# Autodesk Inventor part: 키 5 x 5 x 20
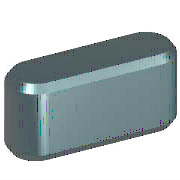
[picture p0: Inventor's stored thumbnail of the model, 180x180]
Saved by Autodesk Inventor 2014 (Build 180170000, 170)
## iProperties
IsCustomPart: 1
Created: 2012-02
Part Number: 키 5 x 5 x 20
Material: 강철, 연강
Description: 키 및 해당 키홈
Document SubType Name: Modeling
Standard: KS B 1311
Designer: mduedu
Standards Organization: KS
Language: ko-KR
Size Designation: 5 x 5 x 20
Categories: <MemberInstance><Categories><Category DisplayName="샤프트 부품" InternalName="7f7aeb1f-a693-4053-b835-cee3144e0d98" Mnemonic="SHFT"><Category DisplayName="키" Interna
Density: 1 g/cm^3
Appearance: 노란색
Author: mduedu
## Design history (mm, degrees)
workplane "Work Plane1"
workplane "Work Plane2"
sketch "스케치1"
  geometry: L1 (2.5, 2.5)-(17.5, 2.5); L2 (17.5, -2.5)-(2.5, -2.5); L3 (0, 9.4)-(0, -7.4) reference; L4 (-5, 0)-(30, 0) reference; L5 (20, 0)-(20, 7); A1 r 2.5 centre (2.5, 0) between (2.5, 2.5) and (2.5, -2.5); A2 r 2.5 centre (17.5, 0) between (17.5, -2.5) and (17.5, 2.5)
  constraints: 6 end point, 5 point on circle, 4 tangent, 3 point on line, 2 centre point, 1 horizontal, 1 parallel, 1 perpendicular
  dimensions: "d0" = 2.5 radius of A1 (= 0.5 x PB); "d13" = 2.5 radius of A2 (= 0.5 x PB); "d14" = 20 distance between parallel lines of L5 L3 (= NLG)
extrude "본체1" new body sketch "스케치1" taper "d3" = 0 deg; stored distance "d4" = 10
workplane "Work Plane3"
body "Solid1"
chamfer "모따기1" distance "d8" = 0.4 (= PHH); stored, may be unused: second distance "d9" = 0.4 (= PHH), angle "d15" = 45 deg
other parameters: "d1" = -3 (= -PNT), "d2" = 2 (= PH - PNT), "NLG" = 20 [user parameter; used in 3 equation terms], "PB" = 5 [user parameter; used in 2 equation terms], "PNT" = 3 [user parameter; used in 2 equation terms], "PH" = 5 [user parameter; used in 1 equation term], "PHH" = 0.4 [user parameter; used in 2 equation terms], "d10" = 0, "d16" = 0, "d17" = 0, "d18" = 0, "WDMIN" = 12 [user parameter], "WDMAX" = 17 [user parameter], "RR" = 0.16 [user parameter], "PUEB" = 2.3 [user parameter]
